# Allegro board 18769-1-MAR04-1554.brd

Outline 198 x 90 mm; copper layers: TOP, TOP_-MB, L2GND, L3_-MB, L3, L4VCC, L5_-MB, L5, L6_-MB, L6, L7VCC, L8_-MB, L8, L9GND, BOTTOM_-MB, BOTTOM. Coordinates in mm from the lower left corner of the outline.

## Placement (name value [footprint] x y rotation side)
AFTP2402  AFTE14P-GP  [AFTE14P-75]  26.02 6.33 0 top
AFTP2507  AFTE14P-GP  [AFTE14P-75]  17.26 9.08 90 top
AFTP2508  AFTE14P-GP  [AFTE14P-75]  16.06 7.47 90 top
AFTP2601  AFTE14P-GP  [AFTE14P-75]  190.34 36.67 270 top
AFTP2602  AFTE14P-GP  [AFTE14P-75]  190.06 34.76 270 top
AFTP2603  AFTE14P-GP  [AFTE14P-75]  189.4 38.35 349 top
AFTP2604  AFTE14P-GP  [AFTE14P-75]  191.05 33.08 270 top
AFTP2901  AFTE14P-GP  [AFTE14P-75]  159.87 11 0 top
AFTP2902  AFTE14P-GP  [AFTE14P-75]  161.34 12.3 0 top
AFTP2903  AFTE14P-GP  [AFTE14P-75]  165.65 10.14 270 top
AFTP2904  AFTE14P-GP  [AFTE14P-75]  162.7 10.92 270 top
AFTP3301  AFTE14P-GP  [AFTE14P-75]  15.4 4.28 0 top
AFTP3302  AFTE14P-GP  [AFTE14P-75]  17.38 4.8 0 top
AFTP4301  AFTE14P-GP  [AFTE14P-75]  36.43 72.73 0 top
AFTP4302  AFTE14P-GP  [AFTE14P-75]  34.91 73.97 0 top
AFTP4303  AFTE14P-GP  [AFTE14P-75]  36.03 81.16 0 top
AFTP4304  AFTE14P-GP  [AFTE14P-75]  32.77 72.66 0 top
AFTP4305  AFTE14P-GP  [AFTE14P-75]  35.07 79.43 0 top
AFTP4306  AFTE14P-GP  [AFTE14P-75]  111.37 9.74 0 top
AFTP4307  AFTE14P-GP  [AFTE14P-75]  117.04 4.11 0 top
AFTP4308  AFTE14P-GP  [AFTE14P-75]  73.1 6.85 270 top
AFTP4309  AFTE14P-GP  [AFTE14P-75]  112.69 14.19 0 top
AFTP4310  AFTE14P-GP  [AFTE14P-75]  109.62 13.57 0 top
AFTP4311  AFTE14P-GP  [AFTE14P-75]  109.61 11.43 0 top
AFTP4312  AFTE14P-GP  [AFTE14P-75]  114.62 6.28 180 top
AFTP4313  AFTE14P-GP  [AFTE14P-75]  112.7 6.14 0 top
AFTP4314  AFTE14P-GP  [AFTE14P-75]  110.79 6.33 180 top
AFTP4316  AFTE14P-GP  [AFTE14P-75]  34.1 81.08 0 top
AFTP4317  AFTE14P-GP  [AFTE14P-75]  195.78 14.36 0 top
AFTP5001  AFTE14P-GP  [AFTE14P-75]  95.4 82.19 270 bottom
AFTP6108  AFTE14P-GP  [AFTE14P-75]  168.46 18.75 270 top
AFTP6109  AFTE14P-GP  [AFTE14P-75]  159.08 17.43 270 top
AFTP6110  AFTE14P-GP  [AFTE14P-75]  170.49 16.29 270 top
AFTP6111  AFTE14P-GP  [AFTE14P-75]  163.66 19.61 270 top
AFTP6112  AFTE14P-GP  [AFTE14P-75]  166.98 20.92 270 top
AFTP6113  AFTE14P-GP  [AFTE14P-75]  167.46 31.67 270 top
AFTP6114  AFTE14P-GP  [AFTE14P-75]  165.66 19.41 270 top
AFTP6115  AFTE14P-GP  [AFTE14P-75]  157.52 16.15 270 top
AFTP6301  AFTE14P-GP  [AFTE14P-75]  119.8 29.31 0 top
AFTP6303  AFTE14P-GP  [AFTE14P-75]  124.98 32.49 180 bottom
AFTP6304  AFTE14P-GP  [AFTE14P-75]  115.48 19.14 0 top
AFTP6501  AFTE14P-GP  [AFTE14P-75]  43.11 4.82 0 top
AFTP6502  AFTE14P-GP  [AFTE14P-75]  38.24 3.31 0 top
AFTP6503  AFTE14P-GP  [AFTE14P-75]  39.25 4.98 0 top
AFTP6504  AFTE14P-GP  [AFTE14P-75]  60.66 5.7 0 top
AFTP6505  AFTE14P-GP  [AFTE14P-75]  41.17 5.03 0 top
AFTP6506  AFTE14P-GP  [AFTE14P-75]  40.99 7.05 0 top
AFTP6507  AFTE14P-GP  [AFTE14P-75]  51.79 8.64 0 top
AFTP6508  AFTE14P-GP  [AFTE14P-75]  41.47 9.02 0 top
AFTP6509  AFTE14P-GP  [AFTE14P-75]  42.93 6.86 0 top
AFTP6510  AFTE14P-GP  [AFTE14P-75]  45.23 9.1 0 top
AFTP6511  AFTE14P-GP  [AFTE14P-75]  50.3 6.63 0 top
AFTP6512  AFTE14P-GP  [AFTE14P-75]  44.88 6.87 0 top
AFTP6513  AFTE14P-GP  [AFTE14P-75]  50.16 4.65 0 top
AFTP6514  AFTE14P-GP  [AFTE14P-75]  46.55 5.78 0 top
AFTP6515  AFTE14P-GP  [AFTE14P-75]  46.95 10.09 0 top
AFTP6516  AFTE14P-GP  [AFTE14P-75]  48.42 6.12 0 top
AFTP6517  AFTE14P-GP  [AFTE14P-75]  47.85 4.29 0 top
AFTP6518  AFTE14P-GP  [AFTE14P-75]  49.14 8.17 0 top
AFTP6519  AFTE14P-GP  [AFTE14P-75]  52.02 5.72 0 top
AFTP6520  AFTE14P-GP  [AFTE14P-75]  54.77 6.39 0 top
AFTP6521  AFTE14P-GP  [AFTE14P-75]  56.35 5.21 0 top
AFTP6522  AFTE14P-GP  [AFTE14P-75]  59.21 4.22 0 top
AFTP6523  AFTE14P-GP  [AFTE14P-75]  58.34 5.99 0 top
AFTP6524  AFTE14P-GP  [AFTE14P-75]  54.48 2.58 0 top
AFTP6525  AFTE14P-GP  [AFTE14P-75]  132.41 7.36 0 top
AFTP6529  AFTE14P-GP  [AFTE14P-75]  21.11 9.74 180 top
AFTP6530  AFTE14P-GP  [AFTE14P-75]  33.93 10.22 0 bottom
AFTP6531  AFTE14P-GP  [AFTE14P-75]  120.79 7.63 0 top
AFTP6534  AFTE14P-GP  [AFTE14P-75]  126.71 10.8 0 bottom
AFTP6535  AFTE14P-GP  [AFTE14P-75]  124.3 9.51 0 bottom
AFTP6536  AFTE14P-GP  [AFTE14P-75]  118.88 4.66 0 top
AFTP6537  AFTE14P-GP  [AFTE14P-75]  125.84 8.44 0 top
AFTP6538  AFTE14P-GP  [AFTE14P-75]  62.05 4.3 180 top
AFTP6539  AFTE14P-GP  [AFTE14P-75]  53.71 4.72 0 top
AFTP6607  AFTE14P-GP  [AFTE14P-75]  162.03 14.41 0 top
AFTP6608  AFTE14P-GP  [AFTE14P-75]  171.53 8.99 0 top
BATT1  ACES-CON12-12-GP-U1  [88231-1201-LP]  107.59 6.16 180 bottom
BIOS1  W25Q128JVSIQ-GP  [SOIC8-1H86]  133.76 27.46 270 bottom
C801  SC1U10V2KX-1DLGP  [C402H22]  97.12 73.19 0 bottom
C802  SC1U10V2KX-1DLGP  [C402H22]  93.88 64.4 90 top
C803  SC1U10V2KX-1DLGP  [C402H22]  97.88 49.85 0 top
C804  SC1U10V2KX-1DLGP  [C402H22]  78.45 36.61 270 top
C805  SCD1U16V2KX-3DLGP  [C402H22]  100.17 59.17 0 top
C806  SC1U10V2KX-1DLGP  [C402H22]  100.96 59.15 0 top
C807  SC22U6D3V3MX-1-DL-GP  [C603H40]  138.57 87.82 180 top
C1102  SC1U10V2KX-1DLGP  [C402H22]  74.21 49.79 90 top
C1103  SC1U10V2KX-1DLGP  [C402H22]  69.49 47.17 90 top
C1104  SC1U10V2KX-1DLGP  [C402H22]  67.53 52.59 90 top
C1105  SC1U10V2KX-1DLGP  [C402H22]  72.35 61.42 180 top
C1106  SC1U10V2KX-1DLGP  [C402H22]  71.72 53.52 90 top
C1107  SC1U10V2KX-1DLGP  [C402H22]  69.48 52.63 270 top
C1108  SC1U10V2KX-1DLGP  [C402H22]  97.88 55.36 0 top
C1109  SC1U10V2KX-1DLGP  [C402H22]  98.03 56.5 270 top
C1110  SC1U10V2KX-1DLGP  [C402H22]  96 51.9 270 top
C1111  SC1U10V2KX-1DLGP  [C402H22]  96.02 52.68 270 top
C1112  SC22U6D3V3MX-1-DL-GP  [C603H40]  100.09 57.21 270 top
C1113  SC22U6D3V3MX-1-DL-GP  [C603H40]  112.23 47.13 270 top
C1114  SC1U10V2KX-1DLGP  [C402H22]  101.56 54.09 0 top
C1115  SC22U6D3V3MX-1-DL-GP  [C603H40]  132.21 86.42 270 top
C1116  SC1U10V2KX-1DLGP  [C402H22]  110.77 87.81 180 top
C1117  SC1U10V2KX-1DLGP  [C402H22]  134.76 87.32 180 top
C1118  SC22U6D3V3MX-1-DL-GP  [C603H40]  137.35 87.82 180 top
C1119  SC1U10V2KX-1DLGP  [C402H22]  105.29 58.29 180 top
C1120  SC10U6D3V3MX-DL-GP  [C603H36]  136.11 87.75 180 top
C1121  SC1U10V2KX-1DLGP  [C402H22]  104.53 58.29 180 top
C1122  SC22U6D3V3MX-1-DL-GP  [C603H40]  105.62 54.68 270 top
C1123  SC10U6D3V3MX-DL-GP  [C603H36]  105.9 50.43 0 top
C1128  SC22U6D3V3MX-1-DL-GP  [C603H40]  99.48 54.91 270 top
C1129  SC22U6D3V3MX-1-DL-GP  [C603H40]  102.6 55.75 180 top
C1130  SC22U6D3V3MX-1-DL-GP  [C603H40]  54.04 35.87 90 top
C1131  SC22U6D3V3MX-1-DL-GP  [C603H40]  84.15 35.8 180 top
C1132  SC22U6D3V3MX-1-DL-GP  [C603H40]  86.75 34.25 180 top
C1133  SC22U6D3V3MX-1-DL-GP  [C603H40]  94.04 49.86 270 top
C1134  SC22U6D3V3MX-1-DL-GP  [C603H40]  84.27 49.76 270 top
C1135  SC22U6D3V3MX-1-DL-GP  [C603H40]  86.65 49.76 90 top
C1136  SC10U6D3V3MX-DL-GP  [C603H36]  82.46 47.17 270 top
C1137  SC10U6D3V3MX-DL-GP  [C603H36]  73.42 33.55 180 top
C1138  SC10U6D3V3MX-DL-GP  [C603H36]  87.47 36.17 270 top
C1139  SCD1U16V2KX-3DLGP  [C402H22]  77.93 46.43 180 top
C1140  SCD1U16V2KX-3DLGP  [C402H22]  91.84 35.53 180 top
C1141  SCD1U16V2KX-3DLGP  [C402H22]  78.59 35.58 270 top
C1142  SCD1U16V2KX-3DLGP  [C402H22]  95.82 24.34 0 top
C1201  SC10U6D3V3MX-DL-GP  [C603H36]  100.74 20.47 270 top
C1209  SC10U6D3V3MX-DL-GP  [C603H36]  58.31 35.76 135 top
C1210  SC10U6D3V3MX-DL-GP  [C603H36]  99.91 26.98 270 top
C1211  SC10U6D3V3MX-DL-GP  [C603H36]  96.86 28.17 90 top
C1214  SCD047U25V2KX-4-GP  [C402H22]  59.52 24.82 0 top
C1215  SCD047U25V2KX-4-GP  [C402H22]  52.03 35.62 270 top
C1218  SC1U10V2KX-1DLGP  [C402H22]  60.54 29.14 180 top
C1219  SC1U10V2KX-1DLGP  [C402H22]  110.54 32.55 270 top
C1220  SC1U10V2KX-1DLGP  [C402H22]  93.81 31.81 270 top
C1221  SC1U10V2KX-1DLGP  [C402H22]  98.91 25.57 180 top
C1226  SC1U10V2KX-1DLGP  [C402H22]  78.83 24.31 0 top
C1227  SC1U10V2KX-1DLGP  [C402H22]  98.14 25.57 180 top
C1229  SCD047U25V2KX-4-GP  [C402H22]  78.46 20.11 270 top
C1230  SCD047U25V2KX-4-GP  [C402H22]  70.32 31.81 270 top
C1231  SC1U10V2KX-1DLGP  [C402H22]  62.95 25.84 0 top
C1242  SC1U10V2KX-1DLGP  [C402H22]  62.08 30.69 270 top
C1244  SC1U10V2KX-1DLGP  [C402H22]  79.97 25.84 180 top
C1245  SC10U6D3V3MX-DL-GP  [C603H36]  70.32 35.36 270 top
C1247  SC10U6D3V3MX-DL-GP  [C603H36]  49.84 38.04 0 bottom
C1248  SC10U6D3V3MX-DL-GP  [C603H36]  96.86 26.98 90 top
C1249  SC10U6D3V3MX-DL-GP  [C603H36]  81.57 26.52 270 top
C1250  SCD022U16V2KX-3DLGP  [C402H22]  63.26 35.76 0 top
C1251  SCD022U16V2KX-3DLGP  [C402H22]  62.12 34.56 90 top
C1252  SC10U6D3V3MX-DL-GP  [C603H36]  77.66 22.61 90 top
C1253  SC10U6D3V3MX-DL-GP  [C603H36]  96.61 19.49 90 top
C1256  SC1U10V2KX-1DLGP  [C402H22]  115.41 25.37 90 top
C1257  SC1U10V2KX-1DLGP  [C402H22]  59.37 29.89 90 top
C1258  SC1U10V2KX-1DLGP  [C402H22]  59.37 30.68 90 top
C1259  SC1U10V2KX-1DLGP  [C402H22]  42.89 35.74 270 top
C1260  SC1U10V2KX-1DLGP  [C402H22]  42.89 34.98 270 top
C1261  SC1U10V2KX-1DLGP  [C402H22]  42.89 34.22 270 top
C1262  SC1U10V2KX-1DLGP  [C402H22]  42.89 33.46 270 top
C1263  SC1U10V2KX-1DLGP  [C402H22]  96.86 29.14 90 top
C1265  SC10U6D3V3MX-DL-GP  [C603H36]  59.52 21.9 270 top
C1266  SC10U6D3V3MX-DL-GP  [C603H36]  80.16 18.26 90 top
C1268  SC1U10V2KX-1DLGP  [C402H22]  58 20.38 180 top
C1269  SC1U10V2KX-1DLGP  [C402H22]  95.47 16.69 180 top
C1270  SC1U10V2KX-1DLGP  [C402H22]  80.19 16.56 180 top
C1271  SC1U10V2KX-1DLGP  [C402H22]  80.99 16.57 180 top
C1275  SC1U10V2KX-1DLGP  [C402H22]  76.03 35.23 180 top
C1276  SC1U10V2KX-1DLGP  [C402H22]  58.38 22.92 90 top
C1277  SC1U10V2KX-1DLGP  [C402H22]  77.57 20.87 90 top
C1278  SC1U10V2KX-1DLGP  [C402H22]  61.56 20.63 270 top
C1279  SC1U10V2KX-1DLGP  [C402H22]  58.38 23.68 90 top
C1304  SC1U10V2KX-1DLGP  [C402H22]  81.55 22.03 270 top
C1310  SC1U10V2KX-1DLGP  [C402H22]  81.57 28.71 270 top
C1311  SC1U10V2KX-1DLGP  [C402H22]  51.9 38.41 180 top
C1312  SC1U10V2KX-1DLGP  [C402H22]  73.37 31.81 90 top
C1313  SC1U10V2KX-1DLGP  [C402H22]  96.61 24.31 0 top
C1314  SCD047U25V2KX-4-GP  [C402H22]  80.35 21.14 180 top
C1315  SCD047U25V2KX-4-GP  [C402H22]  108.29 31.81 270 top
C1317  SC1U10V2KX-1DLGP  [C402H22]  77.57 19.35 90 top
C1322  SC10U6D3V3MX-DL-GP  [C603H36]  62.19 29.65 270 top
C1323  SC1U10V2KX-1DLGP  [C402H22]  71.84 31.81 90 top
C1324  SC1U10V2KX-1DLGP  [C402H22]  105.24 31.81 270 top
C1325  SC1U10V2KX-1DLGP  [C402H22]  51.14 38.41 180 top
C1326  SC1U10V2KX-1DLGP  [C402H22]  110.54 31.79 270 top
C1329  SCD047U25V2KX-4-GP  [C402H22]  58.76 24.82 0 top
C1330  SCD047U25V2KX-4-GP  [C402H22]  88.23 31.81 270 top
C1331  SC1U10V2KX-1DLGP  [C402H22]  79.21 25.84 180 top
C1332  SC1U10V2KX-1DLGP  [C402H22]  97.38 25.57 180 top
C1333  SC10U6D3V3MX-DL-GP  [C603H36]  59.22 34.96 135 top
C1334  SC10U6D3V3MX-DL-GP  [C603H36]  115.69 24.3 90 top
C1338  SC10U6D3V3MX-DL-GP  [C603H36]  96.61 20.76 90 top
C1339  SCD022U16V2KX-3DLGP  [C402H22]  66.82 35.91 90 top
C1341  SC1U10V2KX-1DLGP  [C402H22]  82.26 24.31 0 top
C1342  SC1U10V2KX-1DLGP  [C402H22]  99.91 29.14 270 top
C1343  SC1U10V2KX-1DLGP  [C402H22]  90.39 34.98 270 top
C1344  SC1U10V2KX-1DLGP  [C402H22]  98.77 29.52 0 top
C1348  SC1U10V2KX-1DLGP  [C402H22]  100.59 19.47 270 top
C1349  SC1U10V2KX-1DLGP  [C402H22]  44.13 27.79 270 top
C1350  SC10U6D3V3MX-DL-GP  [C603H36]  78.45 28.5 90 top
C1351  SC10U6D3V3MX-DL-GP  [C603H36]  99.91 28.17 270 top
C1352  SC1U10V2KX-1DLGP  [C402H22]  98.01 29.52 0 top
C1353  SC1U10V2KX-1DLGP  [C402H22]  99.67 25.57 180 top
C1354  SC1U10V2KX-1DLGP  [C402H22]  101.82 24.31 0 top
C1355  SC1U10V2KX-1DLGP  [C402H22]  80.86 35.49 180 top
C1356  SC10U6D3V3MX-DL-GP  [C603H36]  61.56 19.61 270 top
C1367  SC1U10V2KX-1DLGP  [C402H22]  98.68 16.57 180 top
C1368  SC1U10V2KX-1DLGP  [C402H22]  98.77 18.6 90 top
C1369  SC1U10V2KX-1DLGP  [C402H22]  57.16 20.33 180 top
C1370  SC1U10V2KX-1DLGP  [C402H22]  45.05 19.11 270 top
C1371  SC10U6D3V3MX-DL-GP  [C603H36]  97.62 23.08 180 top
C1372  SC10U6D3V3MX-DL-GP  [C603H36]  59.18 18.79 90 top
C1605  SCD22U16V2KX-DL-GP  [C402H22]  108.75 72.65 90 bottom
C1606  SCD22U16V2KX-DL-GP  [C402H22]  108.75 73.41 90 bottom
C1607  SCD22U16V2KX-DL-GP  [C402H22]  108.75 74.3 90 bottom
C1608  SCD22U16V2KX-DL-GP  [C402H22]  108.75 75.06 90 bottom
C1609  SCD22U16V2KX-DL-GP  [C402H22]  108.75 75.82 90 bottom
C1610  SCD22U16V2KX-DL-GP  [C402H22]  108.75 76.59 90 bottom
C1611  SCD22U16V2KX-DL-GP  [C402H22]  108.75 77.35 90 bottom
C1612  SCD22U16V2KX-DL-GP  [C402H22]  108.75 78.11 90 bottom
C1701  SC220P50V2KX-3DLGP  [C402H22]  131.24 49.07 90 bottom
C1711  SCD1U16V2KX-3DLGP  [C402H22]  91.5 72.74 90 bottom
C1803  SC15P50V2JN-DL-GP  [C402H22]  107.17 36.6 90 top
C1804  SC15P50V2JN-DL-GP  [C402H22]  104.05 36.6 270 top
C1805  SC1U10V2KX-1DLGP  [C402H22]  118.04 26.1 0 top
C1806  SC1U10V2KX-1DLGP  [C402H22]  102.02 38.29 180 bottom
C1807  SC15P50V2JN-DL-GP  [C402H22]  116.26 73.22 270 bottom
C1808  SC15P50V2JN-DL-GP  [C402H22]  114.53 73.22 90 bottom
C2201  SCD1U16V2KX-3DLGP  [C402H22]  99.58 51.63 0 top
C2202  SC1U10V2KX-1DLGP  [C402H22]  106.16 53.26 180 top
C2203  SC1U10V2KX-1DLGP  [C402H22]  104.16 51.64 0 top
C2204  SC1U10V2KX-1DLGP  [C402H22]  107.53 51.76 180 top
C2205  SC1U10V2KX-1DLGP  [C402H22]  112.22 48.46 180 top
C2206  SCD1U16V2KX-3DLGP  [C402H22]  111.45 48.45 180 top
C2207  SCD1U16V2KX-3DLGP  [C402H22]  110.68 48.45 180 top
C2208  SC22U6D3V3MX-1-DL-GP  [C603H40]  105.49 74.51 270 top
C2209  SC1U10V2KX-1DLGP  [C402H22]  105.65 75.49 270 top
C2210  SC1U10V2KX-1DLGP  [C402H22]  105.57 56.26 270 top
C2211  SC1U10V2KX-1DLGP  [C402H22]  106.74 56.87 180 top
C2212  SC1U10V2KX-1DLGP  [C402H22]  106.41 58.03 90 top
C2213  SC1U10V2KX-1DLGP  [C402H22]  102.54 51.16 90 top
C2214  SC1U10V2KX-1DLGP  [C402H22]  110 87.82 180 top
C2215  SC1U10V2KX-1DLGP  [C402H22]  134.89 81.44 0 top
C2216  SC1U10V2KX-1DLGP  [C402H22]  135.01 81.54 180 bottom
C2217  SC1U10V2KX-1DLGP  [C402H22]  104.56 53.17 90 top
C2218  SC4D7U6D3V3KX-DLGP  [C603H36]  113.8 49.59 270 top
C2219  SC1U10V2KX-1DLGP  [C402H22]  112.22 63.49 0 top
C2220  SC22U6D3V3MX-1-DL-GP  [C603H40]  104.9 60.82 90 top
C2221  SCD1U16V2KX-3DLGP  [C402H22]  102.52 51.94 90 top
C2222  SC1U10V2KX-1DLGP  [C402H22]  109.06 55.33 270 top
C2223  SC1U10V2KX-1DLGP  [C402H22]  98.86 53.53 180 top
C2224  SC1U10V2KX-1DLGP  [C402H22]  102 49.76 90 top
C2405  SC100P50V2JN-3DLGP  [C402H22]  18.97 12.36 0 top
C2406  SCD1U16V2KX-3DLGP  [C402H22]  14.72 12.17 90 bottom
C2407  SCD1U16V2KX-3DLGP  [C402H22]  17.19 19.23 270 top
C2408  SCD1U16V2KX-3DLGP  [C402H22]  15.33 20.31 0 bottom
C2410  SCD1U16V2KX-3DLGP  [C402H22]  16.67 14.09 0 top
C2411  SCD1U16V2KX-3DLGP  [C402H22]  17.48 14.08 0 top
C2412  SCD1U16V2KX-3DLGP  [C402H22]  25.14 28.76 0 top
C2413  SCD1U16V2KX-3DLGP  [C402H22]  31.7 21.17 0 top
C2414  SCD1U16V2KX-3DLGP  [C402H22]  19.07 28.06 270 top
C2415  SCD1U16V2KX-3DLGP  [C402H22]  25.93 28.78 0 top
C2416  SCD1U16V2KX-3DLGP  [C402H22]  11.64 18.91 90 bottom
C2418  SC1U10V2KX-1DLGP  [C402H22]  24.57 27.05 0 top
C2421  SCD1U16V2KX-3DLGP  [C402H22]  11.64 18.15 90 bottom
C2422  SCD1U16V2KX-3DLGP  [C402H22]  15.14 21 0 top
C2423  SCD1U16V2KX-3DLGP  [C402H22]  35.1 18.62 270 bottom
C2424  SC18P50V2JN-1DLGP  [C402H22]  14.41 25.56 0 bottom
C2425  SC18P50V2JN-1DLGP  [C402H22]  14.41 24.03 180 bottom
C2427  SC2D2U10V3KX-1DLGP-U  [C603H36]  15.66 27.71 0 bottom
C2428  SCD1U16V2KX-3DLGP  [C402H22]  23.05 26.01 180 top
C2429  SCD1U16V2KX-3DLGP  [C402H22]  22.19 12.8 180 top
C2435  SC2200P50V2KX-2DLGP  [C402H22]  17.11 20.04 270 top
C2436  SC2200P50V2KX-2DLGP  [C402H22]  36.95 16.01 270 bottom
C2441  SC2200P50V2KX-2DLGP  [C402H22]  17.11 20.82 270 top
C2501  SC10U6D3V3MX-DL-GP  [C603H36]  127.74 30.14 90 bottom
C2502  SCD1U16V2KX-3DLGP  [C402H22]  128.04 31.2 90 bottom
C2503  SCD1U16V2KX-3DLGP  [C402H22]  18.86 9.16 0 bottom
C2517  SCD022U16V2KX-3DLGP  [C402H22]  23.83 5.43 90 top
C2525  SC1U10V2KX-1DLGP  [C402H22]  169.94 34.31 180 top
C2601  SC10U6D3V3MX-DL-GP  [C603H36]  125.49 41.89 0 bottom
C2602  SCD1U16V2KX-3DLGP  [C402H22]  128.5 33.89 0 bottom
C2604  SC4D7U6D3V3KX-DLGP  [C603H36]  193.04 38.43 90 top
C2605  SCD1U16V2KX-3DLGP  [C402H22]  192.23 35.82 0 top
C2606  SC470P50V2KX-3DLGP  [C402H22]  94.65 80.54 270 bottom
C2607  SC2200P50V2KX-2DLGP  [C402H22]  126.83 41.42 270 bottom
C2608  SCD1U16V2KX-3DLGP  [C402H22]  123.24 39.08 0 bottom
C2609  SCD1U16V2KX-3DLGP  [C402H22]  123.24 37.6 180 bottom
C2610  SCD1U16V2KX-3DLGP  [C402H22]  128.08 45.99 180 top
C2702  SC2D2U10V3KX-1DLGP-U  [C603H36]  188.33 12.69 270 top
C2703  SC2D2U10V3KX-1DLGP-U  [C603H36]  188.32 11.5 90 top
C2704  SCD1U16V2KX-3DLGP  [C402H22]  187.68 18.14 90 top
C2705  SC2D2U10V3KX-1DLGP-U  [C603H36]  188.12 17.15 90 top
C2706  SCD1U16V2KX-3DLGP  [C402H22]  185.94 11.4 270 top
C2707  SC10U6D3V3MX-DL-GP  [C603H36]  187.38 9.5 90 top
C2708  SC2D2U10V3KX-1DLGP-U  [C603H36]  189.88 17.6 0 top
C2709  SC2D2U10V3KX-1DLGP-U  [C603H36]  187.8 15.77 270 top
C2710  SC10U6D3V3MX-DL-GP  [C603H36]  187.02 20.34 180 top
C2711  SC10U6D3V3MX-DL-GP  [C603H36]  188.19 20.31 0 top
C2713  SC10U6D3V3MX-DL-GP  [C603H36]  184.33 22.31 180 top
C2714  SCD1U16V2KX-3DLGP  [C402H22]  184.52 20.67 90 top
C2715  SC10U6D3V3MX-DL-GP  [C603H36]  182.32 9.93 0 top
C2717  SC10U6D3V3MX-DL-GP  [C603H36]  180.38 21 270 top
C2718  SCD1U16V2KX-3DLGP  [C402H22]  179.97 20.03 270 top
C2720  SC10U6D3V3MX-DL-GP  [C603H36]  177.01 19.5 270 top
C2721  SCD1U16V2KX-3DLGP  [C402H22]  177.45 18.5 270 top
C2722  SC10U6D3V3MX-DL-GP  [C603H36]  176.67 14.72 270 top
C2723  SC4D7U6D3V3KX-DLGP  [C603H36]  175.82 10.56 0 top
C2735  SCD1U16V2KX-3DLGP  [C402H22]  180.5 10.56 180 top
C2739  SC100P50V2JN-3DLGP  [C402H22]  176.21 8.96 270 top
C2740  SC2D2U10V3KX-1DLGP-U  [C603H36]  172.76 12.78 270 top
C2741  SCD1U16V2KX-3DLGP  [C402H22]  177.87 10.98 0 top
C2907  SC10U6D3V3MX-DL-GP  [C603H36]  185.5 9.31 0 top
C2908  SC10U6D3V3MX-DL-GP  [C603H36]  184.31 9.31 0 top
C2909  SC10U6D3V3MX-DL-GP  [C603H36]  180.48 9.05 90 top
C3301  SC6P50V2CN-1-NL-GP  [C402H22]  6.77 18.06 270 bottom
C3302  SC4D7U6D3V3KX-DLGP  [C603H36]  4.01 13.72 90 bottom
C3303  SCD1U16V2KX-3DLGP  [C402H22]  3.74 10.31 90 bottom
C3304  SC2D2U10V3KX-1DLGP-U  [C603H36]  6.55 7.86 180 bottom
C3305  SCD1U16V2KX-3DLGP  [C402H22]  7.55 7.63 180 bottom
C3307  SC2D2U10V3KX-1DLGP-U  [C603H36]  2 8.86 90 bottom
C3308  SCD1U16V2KX-3DLGP  [C402H22]  1.72 9.85 90 bottom
C3309  SCD1U16V2KX-3DLGP  [C402H22]  11.87 16.07 0 bottom
C3310  SC1U10V2KX-1DLGP  [C402H22]  3.52 15.85 90 bottom
C3311  SC1U10V2KX-1DLGP  [C402H22]  7.98 17.77 0 bottom
C3312  SC4D7U6D3V3KX-DLGP  [C603H36]  3.95 11.28 90 bottom
C3313  SC6P50V2CN-1-NL-GP  [C402H22]  5.59 8.01 180 bottom
C4001  SC470P50V2KX-3DLGP  [C402H22]  62 11.4 90 bottom
C4002  SC470P50V2KX-3DLGP  [C402H22]  62 10.59 90 bottom
C4003  SCD22U10V2KX-2-GP  [C402H22]  68.5 10.8 270 bottom
C4004  SC10U25V5KX-DL-GP  [C805H58]  60.27 10.36 0 bottom
C4005  SC10U25V5KX-DL-GP  [C805H58]  58.51 11.67 180 bottom
C4006  SC10U6D3V3MX-DL-GP  [C603H36]  103.28 32.06 90 top
C4007  SCD1U16V2KX-3DLGP  [C402H22]  93.97 34.45 270 top
C4008  SC10U6D3V3MX-DL-GP  [C603H36]  112.41 87.08 90 top
C4009  SC2D2U10V3KX-1DLGP-U  [C603H36]  12.74 28.44 180 top
C4010  SCD1U16V2KX-3DLGP  [C402H22]  107.83 81.23 270 top
C4012  SC10U6D3V3MX-DL-GP  [C603H36]  138.64 84.09 0 top
C4013  SC10U6D3V3MX-DL-GP  [C603H36]  132.21 85.21 270 top
C4031  SC1U10V2KX-1DLGP  [C402H22]  132.89 84.19 270 top
C4032  SC1U10V2KX-1DLGP  [C402H22]  100.32 33.85 0 top
C4034  SCD1U16V2KX-3DLGP  [C402H22]  132.45 82.9 0 top
C4035  SC1U10V2KX-1DLGP  [C402H22]  89.92 33.73 180 top
C4037  SCD1U16V2KX-3DLGP  [C402H22]  195.63 16.39 90 top
C4038  SC1U10V2KX-1DLGP  [C402H22]  194.42 15.6 270 top
C4039  SCD1U16V2KX-3DLGP  [C402H22]  195.02 17.33 90 top
C4040  SCD1U25V2KX-1-DL-GP  [C402H22]  107.12 86.93 180 top
C4043  SC1U10V2KX-1DLGP  [C402H22]  108.32 86.19 270 top
C4301  SC1U50V3KX-1-GP  [C603H36]  30.44 79.8 270 top
C4302  SCD1U25V2KX-1-DL-GP  [C402H22]  32.32 79.66 180 top
C4303  SCD01U25V2KX-3DLGP  [C402H22]  27.33 79.09 180 top
C4304  SCD01U25V2KX-3DLGP  [C402H22]  28.86 79.6 180 top
C4305  SCD01U25V2KX-3DLGP  [C402H22]  28.1 79.6 180 top
C4306  SC10U25V5KX-DL-GP  [C805H58]  26.3 70.1 270 bottom
C4344  SC1KP50V2KX-1DLGP  [C402H22]  35.93 60.32 90 bottom
C5501  SCD1U16V2KX-3DLGP  [C402H22]  46.53 76.12 0 top
C5502  SC4D7U6D3V3KX-DLGP  [C603H36]  63.26 76.51 0 bottom
C5503  SC4D7U6D3V3KX-DLGP  [C603H36]  57.61 80.84 0 top
C5504  SCD1U16V2KX-3DLGP  [C402H22]  47.31 76.13 0 top
C5505  SC22U6D3V3MX-1-DL-GP  [C603H40]  58.24 76 0 bottom
C5506  SCD1U16V2KX-3DLGP  [C402H22]  44.95 76.13 0 top
C5507  SCD1U16V2KX-3DLGP  [C402H22]  39.95 81.87 270 top
C5508  SC1U10V2KX-1DLGP  [C402H22]  39.96 81.11 270 top
C5509  SCD1U16V2KX-3DLGP  [C402H22]  45.71 76.13 0 top
C5510  SCD1U16V2KX-3DLGP  [C402H22]  43.42 76.13 0 top
C5511  SCD1U16V2KX-3DLGP  [C402H22]  44.18 76.13 0 top
C5512  SCD1U25V2KX-1-DL-GP  [C402H22]  40.47 76.38 270 bottom
C5513  SC1KP50V2KX-1DLGP  [C402H22]  40.6 77.38 270 bottom
C5514  SC10U25V5KX-DL-GP  [C805H58]  40.25 74.83 270 bottom
C5515  SC4D7U6D3V3KX-DLGP  [C603H36]  58.44 76.22 270 top
C5516  SCD1U16V2KX-3DLGP  [C402H22]  60.36 82.58 180 top
C5517  SC10U6D3V3MX-DL-GP  [C603H36]  62.19 82.83 90 top
C5518  SC10U6D3V3MX-DL-GP  [C603H36]  59.01 82.74 180 top
C5554  SCD1U16V2KX-3DLGP  [C402H22]  39.33 72.83 180 top
C5555  SC2200P50V2KX-2DLGP  [C402H22]  38.55 72.95 180 top
C5556  SCD1U25V2KX-1-DL-GP  [C402H22]  38.01 81.13 180 top
C5557  SC2200P50V2KX-2DLGP  [C402H22]  49.92 73.03 270 bottom
C5558  SCD1U16V2KX-3DLGP  [C402H22]  39.76 74.33 270 top
C5701  SCD1U16V2KX-3DLGP  [C402H22]  21.95 42.75 270 bottom
C5702  SCD1U16V2KX-3DLGP  [C402H22]  23.74 53.27 270 top
C5703  SCD1U16V2KX-3DLGP  [C402H22]  23.74 52.51 270 top
C5704  SCD1U16V2KX-3DLGP  [C402H22]  23.74 54.92 270 top
C5705  SCD1U16V2KX-3DLGP  [C402H22]  23.74 54.16 270 top
C5706  SCD1U16V2KX-3DLGP  [C402H22]  23.86 51.49 270 top
C5707  SCD1U16V2KX-3DLGP  [C402H22]  23.86 50.73 270 top
C5708  SCD1U16V2KX-3DLGP  [C402H22]  23.86 49.97 270 top
C5709  SCD1U16V2KX-3DLGP  [C402H22]  23.86 49.2 270 top
C5710  SCD1U16V2KX-3DLGP  [C402H22]  14.64 63.66 270 bottom
C6104  SC10U6D3V3MX-DL-GP  [C603H36]  168.79 30.02 90 top
C6105  SCD1U16V2KX-3DLGP  [C402H22]  170.01 14.32 90 top
C6106  SCD01U25V2KX-3DLGP  [C402H22]  169.99 31.64 90 top
C6107  SCD1U16V2KX-3DLGP  [C402H22]  157.44 24.44 0 bottom
C6108  SCD1U16V2KX-3DLGP  [C402H22]  158.2 24.44 0 bottom
C6109  SC10U6D3V3MX-DL-GP  [C603H36]  167.9 14.91 180 top
C6110  SCD1U16V2KX-3DLGP  [C402H22]  169.81 13.5 90 top
C6111  SCD01U25V2KX-3DLGP  [C402H22]  168.82 32.08 180 top
C6302  SCD22U10V2KX-2-GP  [C402H22]  126.37 27.85 270 bottom
C6303  SCD22U10V2KX-2-GP  [C402H22]  126.37 27.09 270 bottom
C6304  SC33P50V2JN-3DLGP  [C402H22]  115.87 32.42 270 top
C6305  SC33P50V2JN-3DLGP  [C402H22]  115.87 31.64 270 top
C6306  SCD047U25V2KX-4-GP  [C402H22]  115.18 16.39 270 top
C6307  SCD1U16V2KX-3DLGP  [C402H22]  115.9 30.81 270 top
C6308  SCD047U25V2KX-4-GP  [C402H22]  115.16 17.18 270 top
C6311  SCD22U10V2KX-2-GP  [C402H22]  125.95 24.96 270 bottom
C6312  SCD22U10V2KX-2-GP  [C402H22]  125.95 24.2 270 bottom
C6313  SCD22U10V2KX-2-GP  [C402H22]  127.05 23.38 270 bottom
C6314  SCD22U10V2KX-2-GP  [C402H22]  127.05 22.62 270 bottom
C6315  SCD22U10V2KX-2-GP  [C402H22]  127.13 21.81 270 bottom
C6316  SCD22U10V2KX-2-GP  [C402H22]  127.13 21.05 270 bottom
C6317  SC22U6D3V3MX-1-DL-GP  [C603H40]  115.72 21.93 180 top
C6318  SC22U6D3V3MX-1-DL-GP  [C603H40]  116.92 21.93 180 top
C6401  SCD1U16V2KX-3DLGP  [C402H22]  9.14 72.93 90 top
C6402  SC1U10V2KX-1DLGP  [C402H22]  16.88 66.76 270 top
C6501  SCD1U16V2KX-3DLGP  [C402H22]  20.6 10 90 bottom
C6504  SCD1U16V2KX-3DLGP  [C402H22]  24.28 6.34 270 top
C6505  SCD1U16V2KX-3DLGP  [C402H22]  118.75 6.72 270 top
C6701  SC1U10V2KX-1DLGP  [C402H22]  15.27 47.3 0 bottom
C6702  SC1U10V2KX-1DLGP  [C402H22]  15.5 43.65 180 bottom
C6703  SC1U10V2KX-1DLGP  [C402H22]  15.69 45.7 180 bottom
C6715  SCD1U16V2KX-3DLGP  [C402H22]  13.22 46.62 0 top
C7005  SCD1U16V2KX-3DLGP  [C402H22]  193.54 32.09 270 top
C7006  SC10U6D3V3MX-DL-GP  [C603H36]  193.23 33.08 270 top
C7101  SCD1U25V2KX-1-DL-GP  [C402H22]  19.27 42.6 180 top
C7102  SCD1U25V2KX-1-DL-GP  [C402H22]  18.5 42.6 180 top
C7103  SCD1U16V2KX-3DLGP  [C402H22]  21.88 30.9 180 top
C7104  SCD1U16V2KX-3DLGP  [C402H22]  21.12 30.9 180 top
C7105  SCD1U16V2KX-3DLGP  [C402H22]  20.35 30.9 180 top
C7106  SCD1U16V2KX-3DLGP  [C402H22]  19.59 30.9 180 top
C7107  SCD1U16V2KX-3DLGP  [C402H22]  24.47 35.82 270 top
C7108  SCD1U16V2KX-3DLGP  [C402H22]  24.47 37.35 270 top
C7109  SCD1U16V2KX-3DLGP  [C402H22]  24.47 36.59 270 top
C7110  SCD1U16V2KX-3DLGP  [C402H22]  24.47 38.87 270 top
C7111  SCD1U16V2KX-3DLGP  [C402H22]  24.47 38.11 270 top
C7112  SCD1U16V2KX-3DLGP  [C402H22]  23.99 31.66 270 top
C7113  SCD1U16V2KX-3DLGP  [C402H22]  23.99 32.42 270 top
C7114  SCD1U16V2KX-3DLGP  [C402H22]  24.47 35.06 270 top
C7115  SCD1U25V2KX-1-DL-GP  [C402H22]  17.92 28.33 0 top
C7116  SCD1U25V2KX-1-DL-GP  [C402H22]  17.23 38.23 180 bottom
C7117  SCD1U25V2KX-1-DL-GP  [C402H22]  23.36 41.2 180 top
C7118  SCD1U25V2KX-1-DL-GP  [C402H22]  18.11 34.23 0 bottom
C7119  SC10U6D3V3MX-DL-GP  [C603H36]  18.22 37.82 180 bottom
C7120  SCD33U6D3V1MX-GP  [C0201H13]  12.94 38.33 270 top
C7121  SCD33U6D3V1MX-GP  [C0201H13]  12.94 37.57 270 top
C7122  SCD33U6D3V1MX-GP  [C0201H13]  12.9 29.93 270 top
C7123  SCD33U6D3V1MX-GP  [C0201H13]  12.89 30.7 270 top
C7161  SCD1U25V2KX-1-DL-GP  [C402H22]  16.77 33.07 0 top
C7162  SCD1U25V2KX-1-DL-GP  [C402H22]  16.01 33.07 0 top
C7163  SCD1U25V2KX-1-DL-GP  [C402H22]  16.22 35.95 270 top
C7164  SCD1U25V2KX-1-DL-GP  [C402H22]  16.22 36.71 270 top
C7201  SC2D2U10V3KX-1DLGP-U  [C603H36]  31.76 63.83 180 top
C7202  SC2D2U10V3KX-1DLGP-U  [C603H36]  28.89 65.89 180 top
C7203  SC2D2U10V3KX-1DLGP-U  [C603H36]  31.84 57.46 90 bottom
C7205  SC22U6D3V3MX-1-DL-GP  [C603H40]  22.12 64.97 90 bottom
C7206  SCD1U16V2KX-3DLGP  [C402H22]  22.25 63.99 90 bottom
C7208  SC10U6D3V3MX-DL-GP  [C603H36]  34.51 61.78 90 bottom
C7210  SC1U10V2KX-1DLGP  [C402H22]  28.43 60.02 270 top
C7211  SC10U6D3V3MX-DL-GP  [C603H36]  32.11 62.03 90 top
C7212  SCD22U10V2KX-2-GP  [C402H22]  26.17 59.7 90 top
C7217  SC220P50V2KX-3DLGP  [C402H22]  21.73 56.57 0 bottom
C7218  SC220P50V2KX-3DLGP  [C402H22]  22.39 56.75 90 top
C7244  SCD1U16V2KX-3DLGP  [C402H22]  36.31 64.11 270 bottom
C7301  SC1U25V3KX-1-DLGP  [C603H36]  22.51 58.55 180 bottom
C7302  SCD1U25V2KX-1-DL-GP  [C402H22]  13.14 30.12 180 bottom
C7303  SCD1U25V2KX-1-DL-GP  [C402H22]  12.36 30.03 180 bottom
C7304  SCD1U25V2KX-1-DL-GP  [C402H22]  13.24 35.76 0 bottom
C7305  SC10U25V5KX-DL-GP  [C805H58]  16.03 32.7 270 bottom
C7306  SC1U25V3KX-1-DLGP  [C603H36]  14.28 36.85 0 bottom
C7307  SCD1U25V2KX-1-DL-GP  [C402H22]  11.6 30.03 180 bottom
C7401  SC1500P50V2KX-2-DL-GP  [C402H22]  19.96 65.53 270 top
C7601  SCD22U16V2KX-DL-GP  [C402H22]  128.87 67.75 90 top
C7602  SCD22U16V2KX-DL-GP  [C402H22]  128.87 66.98 90 top
C7603  SCD22U16V2KX-DL-GP  [C402H22]  128.87 69.27 90 top
C7604  SCD22U16V2KX-DL-GP  [C402H22]  128.87 68.51 90 top
C7605  SCD22U16V2KX-DL-GP  [C402H22]  128.87 70.79 90 top
C7606  SCD22U16V2KX-DL-GP  [C402H22]  128.87 70.03 90 top
C7607  SCD22U16V2KX-DL-GP  [C402H22]  128.84 71.64 90 top
C7608  SCD22U16V2KX-DL-GP  [C402H22]  128.84 72.4 90 top
C7610  SC4D7U6D3V3KX-DLGP  [C603H36]  162.17 85.81 270 bottom
C7611  SC4D7U6D3V3KX-DLGP  [C603H36]  162.17 84.6 270 bottom
C7612  SC1U10V2KX-1DLGP  [C402H22]  161.91 87.61 270 bottom
C7613  SC1U10V2KX-1DLGP  [C402H22]  161.89 86.82 270 bottom
C7614  SC1U10V2KX-1DLGP  [C402H22]  149.4 63.18 225 top
C7616  SCD1U25V2KX-1-DL-GP  [C402H22]  156.79 69.67 315 top
C7620  SC4D7U6D3V3KX-DLGP  [C603H36]  157.26 84.36 203 top
C7621  SC4D7U6D3V3KX-DLGP  [C603H36]  158.36 84.81 203 top
C7622  SC1U10V2KX-1DLGP  [C402H22]  155.37 71.28 315 top
C7627  SC10U6D3V3MX-DL-GP  [C603H36]  156.76 84.12 0 bottom
C7628  SC22U6D3V3MX-1-DL-GP  [C603H40]  157.94 84.12 0 bottom
C7629  SC10U6D3V3MX-DL-GP  [C603H36]  159.13 84.14 0 bottom
C7630  SC1U10V2KX-1DLGP  [C402H22]  158.25 68.61 315 top
C7631  SC1U10V2KX-1DLGP  [C402H22]  154.23 70.62 225 top
C7744  SC10U6D3V3MX-DL-GP  [C603H36]  154.12 66.95 315 top
C7745  SC10U6D3V3MX-DL-GP  [C603H36]  157.4 44.12 315 bottom
C7746  SC10U6D3V3MX-DL-GP  [C603H36]  162.29 37.89 90 bottom
C7805  SCD1U16V2KX-3DLGP  [C402H22]  162.9 64.65 180 top
C7807  SC1U10V2KX-1DLGP  [C402H22]  174.41 86.39 0 bottom
C7808  SCD1U16V2KX-3DLGP  [C402H22]  161.96 63.89 0 top
C7810  SC1U10V2KX-1DLGP  [C402H22]  170.55 86.39 0 bottom
C7811  SC1U10V2KX-1DLGP  [C402H22]  171.34 86.39 0 bottom
C7812  SC1U10V2KX-1DLGP  [C402H22]  184.06 69.13 180 bottom
C7815  SC1U10V2KX-1DLGP  [C402H22]  188.94 64.13 90 bottom
C7816  SC1U10V2KX-1DLGP  [C402H22]  174.91 51.26 90 bottom
C7817  SC10U6D3V3MX-DL-GP  [C603H36]  185.07 62.52 0 bottom
C7818  SC22U6D3V3MX-1-DL-GP  [C603H40]  160.29 61.22 225 top
C7819  SC10U6D3V3MX-DL-GP  [C603H36]  183 86.59 0 bottom
C7820  SC22U6D3V3MX-1-DL-GP  [C603H40]  184.27 86.59 0 bottom
C7821  SC22U6D3V3MX-1-DL-GP  [C603H40]  185.54 86.59 0 bottom
C7822  SC22U6D3V3MX-1-DL-GP  [C603H40]  181.8 86.57 0 bottom
C7823  SC10U6D3V3MX-DL-GP  [C603H36]  180.61 86.57 0 bottom
C7825  SC1U10V2KX-1DLGP  [C402H22]  175.22 86.39 0 bottom
C7826  SC1U10V2KX-1DLGP  [C402H22]  186.04 62.57 0 bottom
C7827  SCD1U16V2KX-3DLGP  [C402H22]  162.59 66.4 0 top
C7902  SCD1U16V2KX-3DLGP  [C402H22]  159.08 56.68 315 top
C7905  SCD1U16V2KX-3DLGP  [C402H22]  160.16 55.49 45 top
C7906  SCD1U16V2KX-3DLGP  [C402H22]  160.44 58.33 135 top
C7907  SC20P50V2JN-1-DL-GP  [C402H22]  175.81 41.09 270 bottom
C7908  SC20P50V2JN-1-DL-GP  [C402H22]  172.61 41.09 90 bottom
C7934  SC4D7U6D3V3KX-DLGP  [C603H36]  154.06 60.17 135 top
C7935  SC22U6D3V3MX-1-DL-GP  [C603H40]  155.8 57.84 45 top
C8001  SC4D7U6D3V3KX-DLGP  [C603H36]  163.3 37.29 0 top
C8002  SC4D7U6D3V3KX-DLGP  [C603H36]  156.88 38.8 180 bottom
C8003  SC4D7U6D3V3KX-DLGP  [C603H36]  159.44 85.27 203 top
C8004  SC4D7U6D3V3KX-DLGP  [C603H36]  158.73 59.35 135 top
C8008  SC4D7U6D3V3KX-DLGP  [C603H36]  144.25 42.75 0 top
C8009  SC4D7U6D3V3KX-DLGP  [C603H36]  135.67 42.74 0 top
C8010  SC22U6D3V3MX-1-DL-GP  [C603H40]  154.99 69.44 315 top
C8011  SC1U10V2KX-1DLGP  [C402H22]  162.58 34.93 90 bottom
C8012  SC1U10V2KX-1DLGP  [C402H22]  162.28 36.71 90 bottom
C8013  SC1U10V2KX-1DLGP  [C402H22]  145.25 42.76 0 top
C8014  SC1U10V2KX-1DLGP  [C402H22]  155.56 68.5 315 top
C8015  SC4D7U6D3V3KX-DLGP  [C603H36]  157.29 37.31 0 top
C8016  SC4D7U6D3V3KX-DLGP  [C603H36]  158.56 37.31 0 top
C8017  SC22U6D3V3MX-1-DL-GP  [C603H40]  158.05 38.81 180 bottom
C8018  SC1U10V2KX-1DLGP  [C402H22]  142.21 42.66 0 top
C8019  SC4D7U6D3V3KX-DLGP  [C603H36]  147.56 42.62 0 top
C8020  SC4D7U6D3V3KX-DLGP  [C603H36]  138.04 48.28 180 top
C8021  SC4D7U6D3V3KX-DLGP  [C603H36]  136.77 48.28 180 top
C8022  SC4D7U6D3V3KX-DLGP  [C603H36]  152.35 65.31 315 top
C8023  SC4D7U6D3V3KX-DLGP  [C603H36]  159.24 38.81 180 bottom
C8024  SC4D7U6D3V3KX-DLGP  [C603H36]  153.29 67.79 315 top
C8025  SC4D7U6D3V3KX-DLGP  [C603H36]  156.05 60.5 315 top
C8027  SC22U6D3V3MX-1-DL-GP  [C603H40]  160.43 38.83 180 bottom
C8028  SC1U10V2KX-1DLGP  [C402H22]  155.1 82.73 201 top
C8029  SCD1U16V2KX-3DLGP  [C402H22]  155.82 83.01 201 top
C8030  SC4D7U6D3V3KX-DLGP  [C603H36]  162.44 33.89 90 bottom
C8031  SC4D7U6D3V3KX-DLGP  [C603H36]  160.58 41.72 315 bottom
C8032  SC4D7U6D3V3KX-DLGP  [C603H36]  157.82 62.39 315 top
C8033  SC22U6D3V3MX-1-DL-GP  [C603H40]  162.12 37.29 0 top
C8034  SCD1U16V2KX-3DLGP  [C402H22]  156.56 83.3 201 top
C8035  SCD1U16V2KX-3DLGP  [C402H22]  159.46 58.68 135 top
C8036  SC1U10V2KX-1DLGP  [C402H22]  158.54 57.23 315 top
C8037  SCD1U16V2KX-3DLGP  [C402H22]  159.62 54.95 45 top
C8038  SC10U6D3V3MX-DL-GP  [C603H36]  156.88 67.17 315 top
C8039  SC10U6D3V3MX-DL-GP  [C603H36]  155.2 65.48 315 top
C8040  SC10U6D3V3MX-DL-GP  [C603H36]  158.13 65.51 315 top
C8041  SC10U6D3V3MX-DL-GP  [C603H36]  156.42 63.86 315 top
C8042  SC10U6D3V3MX-DL-GP  [C603H36]  154.58 62.35 315 top
C8043  SC10U6D3V3MX-DL-GP  [C603H36]  159.52 64.13 315 top
C8044  SCD1U16V2KX-3DLGP  [C402H22]  158.38 60.45 135 top
C8045  SC10U6D3V3MX-DL-GP  [C603H36]  160.94 37.3 0 top
C8046  SC10U6D3V3MX-DL-GP  [C603H36]  159.75 37.31 0 top
C8101  SCD01U25V2KX-3DLGP  [C402H22]  183.48 42.94 90 top
C8104  SC10U6D3V3MX-DL-GP  [C603H36]  185.05 69.13 180 bottom
C8105  SC1U10V2KX-1DLGP  [C402H22]  187.98 69.15 180 bottom
C8106  SC1U10V2KX-1DLGP  [C402H22]  188.54 65.88 90 bottom
C8107  SC1U10V2KX-1DLGP  [C402H22]  186.82 62.58 0 bottom
C8108  SCD1U16V2KX-3DLGP  [C402H22]  188.38 68 90 bottom
C8109  SC1U10V2KX-1DLGP  [C402H22]  188.38 67.24 90 bottom
C8110  SC1U10V2KX-1DLGP  [C402H22]  184.28 86.15 180 top
C8111  SC1U10V2KX-1DLGP  [C402H22]  183.13 86.1 180 top
C8112  SC1U10V2KX-1DLGP  [C402H22]  181.35 86.1 180 top
C8113  SC10U6D3V3MX-DL-GP  [C603H36]  186.22 69.13 180 bottom
C8114  SC1U10V2KX-1DLGP  [C402H22]  182.11 86.1 180 top
C8115  SCD1U16V2KX-3DLGP  [C402H22]  169.73 86.38 0 bottom
C8116  SCD1U16V2KX-3DLGP  [C402H22]  168.97 86.38 0 bottom
C8117  SCD1U16V2KX-3DLGP  [C402H22]  174.8 86.73 180 top
C8118  SCD1U16V2KX-3DLGP  [C402H22]  173.65 86.39 0 bottom
C8119  SCD1U16V2KX-3DLGP  [C402H22]  172.11 86.38 0 bottom
C8120  SCD1U16V2KX-3DLGP  [C402H22]  172.87 86.38 0 bottom
C8121  SCD1U16V2KX-3DLGP  [C402H22]  177.23 86.78 180 top
C8122  SCD1U16V2KX-3DLGP  [C402H22]  176.39 86.82 180 top
C8123  SCD1U16V2KX-3DLGP  [C402H22]  175.6 86.76 180 top
C8124  SCD1U16V2KX-3DLGP  [C402H22]  184.03 62.52 0 bottom
C8125  SCD1U16V2KX-3DLGP  [C402H22]  170.97 86.73 180 top
C8126  SC820P50V2KX-1-DL-GP  [C402H22]  176.01 86.39 0 bottom
C8201  SCD01U25V2KX-3DLGP  [C402H22]  180.28 87.23 90 top
C8202  SC820P50V2KX-1-DL-GP  [C402H22]  176.81 86.4 0 bottom
C8204  SC1U10V2KX-1DLGP  [C402H22]  187.27 45.43 180 bottom
C8205  SC1U10V2KX-1DLGP  [C402H22]  184.49 45.42 180 bottom
C8206  SC1U10V2KX-1DLGP  [C402H22]  185.27 45.42 180 bottom
C8207  SC10U6D3V3MX-DL-GP  [C603H36]  188.81 62.54 0 bottom
C8209  SCD1U16V2KX-3DLGP  [C402H22]  188.99 58.74 270 top
C8210  SCD1U16V2KX-3DLGP  [C402H22]  176.78 68.37 0 top
C8211  SCD1U16V2KX-3DLGP  [C402H22]  188.05 45.43 180 bottom
C8212  SCD1U16V2KX-3DLGP  [C402H22]  187.61 62.58 0 bottom
C8213  SCD1U16V2KX-3DLGP  [C402H22]  186.14 44.33 0 top
C8214  SCD1U16V2KX-3DLGP  [C402H22]  185.38 44.33 0 top
C8215  SC1U10V2KX-1DLGP  [C402H22]  180.67 44.36 0 top
C8216  SC1U10V2KX-1DLGP  [C402H22]  179.9 44.36 0 top
C8217  SC1U10V2KX-1DLGP  [C402H22]  179.14 44.36 0 top
C8218  SC10U6D3V3MX-DL-GP  [C603H36]  186.27 45.41 180 bottom
C8219  SC1U10V2KX-1DLGP  [C402H22]  178.38 44.36 0 top
C8220  SCD1U16V2KX-3DLGP  [C402H22]  177.62 44.36 0 top
C8221  SCD1U16V2KX-3DLGP  [C402H22]  176.86 44.36 0 top
C8222  SCD1U16V2KX-3DLGP  [C402H22]  176.09 44.36 0 top
C8223  SCD1U16V2KX-3DLGP  [C402H22]  181.43 44.36 0 top
C8224  SC1U10V2KX-1DLGP  [C402H22]  175.33 44.36 0 top
C8225  SCD1U16V2KX-3DLGP  [C402H22]  174.57 44.36 0 top
C8226  SCD1U16V2KX-3DLGP  [C402H22]  186.32 75.8 90 top
C8525  SCD1U25V2KX-1-DL-GP  [C402H22]  146.56 29.59 270 top
C8601  SCD1U16V2KX-3DLGP  [C402H22]  132.12 74.46 0 bottom
C8602  SCD1U16V2KX-3DLGP  [C402H22]  129.38 72.77 270 bottom
C8603  SCD1U16V2KX-3DLGP  [C402H22]  148.57 81.27 180 top
C8604  SCD1U16V2KX-3DLGP  [C402H22]  133.32 73 270 bottom
C8901  SC10U25V3MX-5-GP  [C603H40]  63.64 5.4 180 top
C8902  SC10U25V3MX-5-GP  [C603H40]  75.47 10.41 90 top
C8903  SC10U25V3MX-5-GP  [C603H40]  41.07 10.75 270 top
C9104  SCD1U16V2KX-3DLGP  [C402H22]  188.14 31.74 180 top
C9106  SC10U6D3V3MX-DL-GP  [C603H36]  189.27 25.93 90 top
C9108  SCD1U16V2KX-3DLGP  [C402H22]  188.84 26.94 90 top
C9109  SC10U6D3V3MX-DL-GP  [C603H36]  179.32 27.09 0 top
C9112  SCD1U16V2KX-3DLGP  [C402H22]  180.35 27.58 0 top
C9113  SCD1U16V2KX-3DLGP  [C402H22]  181.17 27.58 0 top
C9201  SC1U10V2KX-1DLGP  [C402H22]  144.4 7.7 90 top
CARD1  SDCARD-8P-10-GP  [503398-0891]  1.32 13.6 90 top
CN1  HRS-CONN20A-2-GP  [DF30FC-20DP-D4V-81]  123.65 75.27 0 bottom
CPU1  WHISKEY-LAKE-GP  [BGA1528M2446-1H52]  90.15 54.21 270 bottom
D1701  RB520S30-GP  [SOD523AKH26]  129.91 56.87 270 bottom
D2401  BAT54C-12-GP  [SOT-23-9H44]  22.48 21.69 90 top
D2402  RB751VM-40TE-17-GP  [SOD323-2513AKH36]  36.04 13.82 90 bottom
D2403  L1SS355T1G-GP  [SOD323AKH44]  23.47 18.28 90 top
D2501  BAT54C-12-GP  [SOT-23-9H44]  16.49 9.27 90 bottom
D2503  BAT54A-11-GP  [SOT-23-9H44]  174.9 33.35 0 top
D2703  BAT54C-12-GP  [SOT-23-9H44]  171.81 5.7 0 top
D2901  BAW56-9-GP-U  [SOT23-2D4-312H44]  191.03 14.6 180 top
D4001  L1SS355T1G-GP  [SOD323AKH44]  12.07 21.1 90 top
D4301  P6AF24A-R1-00001-GP  [D4724AKH44]  39.61 78.66 270 top
D4302  LBAV99LT1G-1-GP  [SOT23-2D4-312H44]  18.37 50.74 0 bottom
D4303  L30ESD24VC3-2-GP  [SOT23-2D4-312H60]  24.27 53.23 180 bottom
D4304  SMF18A-GP  [SOD123AK-2H43]  119.35 4.99 0 bottom
D5501  BAT54C-12-GP  [SOT-23-9H44]  64.6 84.36 270 bottom
D5502  BAT54C-12-GP  [SOT-23-9H44]  63.67 86.97 90 top
D5504  RB551V30-GP  [SOD323AKH38]  37.66 68.11 180 bottom
D5505  RB551V30-GP  [SOD323AKH38]  39.39 70.74 270 top
D5701  BAW56-9-GP-U  [SOT23-2D4-312H44]  14.92 68.17 270 bottom
D6401  BAT54A-11-GP  [SOT-23-9H44]  21.11 73.2 180 top
D6402  RB751V-40-2-GP  [SOD323AKH38]  19.94 65.02 0 bottom
D6701  L1SS355T1G-GP  [SOD323AKH44]  17.55 44.21 180 bottom
D6702  RB751VM-40TE-17-GP  [SOD323-2513AKH36]  20.39 47.35 270 top
D7301  BX310F-R1-00000-GP  [D4724AKH44]  16.39 30.37 90 bottom
D7902  L1SS355T1G-GP  [SOD323AKH44]  160.09 44.39 225 bottom
D8601  BAT54C-12-GP  [SOT-23-9H44]  185.03 40.09 270 bottom
DB1  ACES-CON14-5-GP  [87212-1400N]  26.58 19.17 90 top
DB3  ACES-CON6-58-GP  [50696-00601-001]  33.89 8.79 90 top
DCIN1  ACES-CON8-13-GP-U2  [50224-0080N-W02-U]  31.1 76.6 90 bottom
EC1901  SC10P50V2JN-4DLGP  [C402H22]  119.64 37.26 270 bottom
EC2201  SCD1U16V2KX-3DLGP  [C402H22]  109.23 87.86 180 top
EC2501  SC10P50V2JN-4DLGP  [C402H22]  125.83 25.81 90 bottom
EC2601  SC10P50V2JN-4DLGP  [C402H22]  188.66 36.14 180 top
EC2602  SC10P50V2JN-4DLGP  [C402H22]  188.66 34.39 0 top
EC2701  SC1KP50V2KX-1DLGP  [C402H22]  190.72 9.44 0 top
EC2702  SC1KP50V2KX-1DLGP  [C402H22]  189.96 9.44 0 top
EC2703  SC1KP50V2KX-1DLGP  [C402H22]  181.25 7.66 0 top
EC2704  SC1KP50V2KX-1DLGP  [C402H22]  192.57 16.58 90 top
EC2705  SC1KP50V2KX-1DLGP  [C402H22]  192.57 17.37 90 top
EC2706  SC33P50V2JN-3DLGP  [C402H22]  175.68 17.31 270 top
EC2709  SC22P50V2JN-9-GP  [C402H22]  174.51 16.96 180 top
EC2710  SC22P50V2JN-9-GP  [C402H22]  174.02 15.26 90 top
EC2711  SC22P50V2JN-9-GP  [C402H22]  174.22 18.15 270 top
EC2901  SC1KP50V2KX-1DLGP  [C402H22]  160.52 9.27 90 top
EC2902  SC1KP50V2KX-1DLGP  [C402H22]  158.96 9.65 270 top
EC2903  SC1KP50V2KX-1DLGP  [C402H22]  163.65 9.29 270 top
EC2904  SC1KP50V2KX-1DLGP  [C402H22]  162.14 9.29 90 top
EC4301  SC10U25V5KX-DL-GP  [C805H58]  37 76.06 180 bottom
EC4302  SCD1U25V2KX-1-DL-GP  [C402H22]  36.52 76.27 0 top
EC4303  SCD1U25V2KX-1-DL-GP  [C402H22]  22.34 59.49 270 top
EC4306  SC10P50V2JN-4DLGP  [C402H22]  86.45 14.27 90 top
EC4307  SC1KP50V2KX-1DLGP  [C402H22]  99 12.45 90 bottom
EC4308  SCD1U50V3KX-DL-GP  [C603H35]  98.78 11.44 90 bottom
EC4309  SC10P50V2JN-4DLGP  [C402H22]  112.79 10.74 0 top
EC4310  SC10P50V2JN-4DLGP  [C402H22]  112.79 12.39 180 top
EC4312  SC1KP50V2KX-1DLGP  [C402H22]  37.28 76.27 0 top
EC4401  SC1KP50V2KX-1DLGP  [C402H22]  35.35 71.85 0 bottom
EC4402  SC1KP50V2KX-1DLGP  [C402H22]  25.8 39.04 0 bottom
EC4403  SC1KP50V2KX-1DLGP  [C402H22]  135.22 7.56 0 top
EC4404  SC1KP50V2KX-1DLGP  [C402H22]  134.43 7.56 0 top
EC4405  SC1KP50V2KX-1DLGP  [C402H22]  39.95 10.83 90 bottom
EC4406  SC1KP50V2KX-1DLGP  [C402H22]  135.37 3.19 180 bottom
EC4407  SC1KP50V2KX-1DLGP  [C402H22]  64.65 3.31 180 bottom
EC4408  SC1KP50V2KX-1DLGP  [C402H22]  74.23 11.66 0 bottom
EC5503  SC33P50V2JN-3DLGP  [C402H22]  54.45 78.96 270 top
EC5504  SC33P50V2JN-3DLGP  [C402H22]  57.19 78.45 0 top
EC6401  SC10P50V2JN-4DLGP  [C402H22]  7.82 69.71 180 bottom
EC6402  SC10P50V2JN-4DLGP  [C402H22]  8.43 72.98 270 bottom
EC6501  SC33P50V2JN-3DLGP  [C402H22]  127.88 5.96 0 top
EC6502  SC33P50V2JN-3DLGP  [C402H22]  127.88 7.48 180 top
EC8901  SCD1U16V2KX-3DLGP  [C402H22]  100.68 73.33 180 bottom
EC8902  SCD1U16V2KX-3DLGP  [C402H22]  76.44 72.17 180 bottom
EC8903  SCD1U16V2KX-3DLGP  [C402H22]  77.25 72.15 180 bottom
EC8904  SCD1U16V2KX-3DLGP  [C402H22]  86.63 72.9 180 bottom
EC8905  SCD1U16V2KX-3DLGP  [C402H22]  49.11 56.34 270 top
EC8906  SCD1U16V2KX-3DLGP  [C402H22]  49.11 55.48 270 top
EC8907  SCD1U16V2KX-3DLGP  [C402H22]  104.33 76.38 90 top
EC8908  SCD1U25V2KX-1-DL-GP  [C402H22]  41.52 39.5 90 top
EC8909  SCD1U25V2KX-1-DL-GP  [C402H22]  41.81 70.04 225 top
EC8910  SCD1U25V2KX-1-DL-GP  [C402H22]  134.38 38.54 90 top
EC8911  SCD1U25V2KX-1-DL-GP  [C402H22]  134.89 61.77 45 bottom
EC8912  SCD1U25V2KX-1-DL-GP  [C402H22]  64.3 77.55 180 bottom
EC8913  SCD1U25V2KX-1-DL-GP  [C402H22]  156.73 35.62 90 top
EC8914  SCD1U25V2KX-1-DL-GP  [C402H22]  186.73 33.3 0 top
EC8915  SCD1U25V2KX-1-DL-GP  [C402H22]  130.44 38.05 0 bottom
EC8916  SCD1U25V2KX-1-DL-GP  [C402H22]  101.79 87.18 270 bottom
EC8917  SCD1U25V2KX-1-DL-GP  [C402H22]  40.94 44.63 90 top
EC8918  SC1KP50V2KX-1DLGP  [C402H22]  24.52 64.95 0 top
EC8919  SC1KP50V2KX-1DLGP  [C402H22]  51.88 12.37 270 bottom
EC8920  SC1KP50V2KX-1DLGP  [C402H22]  64.2 2.88 270 top
EC8921  SC1KP50V2KX-1DLGP  [C402H22]  33.11 28.83 270 bottom
EC8922  SC1KP50V2KX-1DLGP  [C402H22]  26.81 34.45 270 top
EC8923  SC1KP50V2KX-1DLGP  [C402H22]  189.24 24.92 90 top
EC8924  SC1KP50V2KX-1DLGP  [C402H22]  163.38 15.04 180 top
EC8925  SC1KP50V2KX-1DLGP  [C402H22]  90.87 8.82 270 top
EC8926  SC1KP50V2KX-1DLGP  [C402H22]  66.26 11.99 0 top
EC8927  SC1KP50V2KX-1DLGP  [C402H22]  169.86 10.34 270 top
EC8928  SC1KP50V2KX-1DLGP  [C402H22]  64.22 2.11 270 top
EC8929  SC1KP50V2KX-1DLGP  [C402H22]  69.25 9.66 0 bottom
EC8930  SC1KP50V2KX-1DLGP  [C402H22]  80.81 24.31 0 top
EC8931  SC1KP50V2KX-1DLGP  [C402H22]  63.74 25.58 0 top
EC8932  SC1KP50V2KX-1DLGP  [C402H22]  79.64 24.31 0 top
EC8933  SC1KP50V2KX-1DLGP  [C402H22]  42.94 32.64 270 top
EC8934  SC1KP50V2KX-1DLGP  [C402H22]  52.67 38.41 180 top
EC8937  SCD1U16V2KX-3DLGP  [C402H22]  85.82 72.92 180 bottom
EC8938  SCD1U16V2KX-3DLGP  [C402H22]  83.35 72.32 180 bottom
EC8939  SC1KP50V2KX-1DLGP  [C402H22]  50.28 38.41 180 top
EC8940  SC1KP50V2KX-1DLGP  [C402H22]  92.63 35.52 180 top
EC8941  SC1KP50V2KX-1DLGP  [C402H22]  101.11 32.68 180 top
EC8942  SC1KP50V2KX-1DLGP  [C402H22]  70.68 36.4 270 top
EC8943  SC1KP50V2KX-1DLGP  [C402H22]  32.58 82.05 270 top
EC8944  SC1KP50V2KX-1DLGP  [C402H22]  64.55 11.87 0 top
EC8945  SC1KP50V2KX-1DLGP  [C402H22]  60.03 76.64 0 top
EC8946  SC1KP50V2KX-1DLGP  [C402H22]  119.95 17.23 90 top
EC8947  SC1KP50V2KX-1DLGP  [C402H22]  127.11 81.79 270 top
EC8948  SC1KP50V2KX-1DLGP  [C402H22]  16.45 57.08 90 top
EC8949  SC1KP50V2KX-1DLGP  [C402H22]  194.43 35.83 0 top
EC8950  SC1KP50V2KX-1DLGP  [C402H22]  179.72 23.44 0 top
EC8951  SC1KP50V2KX-1DLGP  [C402H22]  16.57 59.35 90 top
EC8952  SC1KP50V2KX-1DLGP  [C402H22]  61.94 10.11 270 top
EC8953  SC1KP50V2KX-1DLGP  [C402H22]  188.71 7.19 90 top
EC8954  SC1KP50V2KX-1DLGP  [C402H22]  22.35 5.46 0 top
ED301  AZ5125-02S-R7G-GP  [SOT23-2D4-312H46]  95.02 75.02 270 bottom
ED1701  TVL5VB1-DFN1006-2L-GP  [SOD882-10D6-1H20]  131.17 58.75 0 bottom
ED1702  TVL5VB1-DFN1006-2L-GP  [SOD882-10D6-1H20]  175.94 31.04 0 top
ED1703  TVL5VB1-DFN1006-2L-GP  [SOD882-10D6-1H20]  127.7 53.69 180 top
ED1704  TVL5VB1-DFN1006-2L-GP  [SOD882-10D6-1H20]  72.45 12.3 90 bottom
ED1706  AZ5725-01FDR7G-GP  [SOD882-10D6-1H20]  131.5 52.63 180 bottom
ED1707  AZ5725-01FDR7G-GP  [SOD882-10D6-1H20]  93.1 71.38 270 bottom
ED4304  LBAV99LT1G-1-GP  [SOT23-2D4-312H44]  80.12 11.55 0 top
ED4305  LBAV99LT1G-1-GP  [SOT23-2D4-312H44]  115.7 11.3 180 top
ED4306  LBAV99LT1G-1-GP  [SOT23-2D4-312H44]  115.69 8.79 180 top
ED5501  AZC099-04S-2-GP  [SOT-6H58]  53.75 74.64 90 bottom
ED5502  PUSB3F96-GP  [DFN10G2510-1H20]  48.73 75.75 180 bottom
ED5503  AZ5725-01FDR7G-GP  [SOD882-10D6-1H20]  51.81 77.36 0 top
ED5504  AZ5725-01FDR7G-GP  [SOD882-10D6-1H20]  109.06 59.78 270 top
ED5701  L05ESDL5V0NA-4-GP  [SLP2510P8-1H22]  18.76 53.65 90 top
ED5702  L05ESDL5V0NA-4-GP  [SLP2510P8-1H22]  18.5 50.47 90 top
ED5703  L05ESDL5V0NA-4-GP  [SLP2510P8-1H22]  15.28 63.33 180 top
ED6701  AZ5725-01FDR7G-GP  [SOD882-10D6-1H20]  116.28 5.5 90 top
ED7301  L05ESDL5V0NA-4-GP  [SLP2510P8-1H22]  14.58 37.13 90 top
ED7302  L05ESDL5V0NA-4-GP  [SLP2510P8-1H22]  14.57 31.12 90 top
ED7303  L05ESDL5V0NA-4-GP  [SLP2510P8-1H22]  12.72 40.88 0 top
ED7304  L05ESDL5V0NA-4-GP  [SLP2510P8-1H22]  16.47 43.47 0 top
ED9201  L05ESDL5V0NA-4-GP  [SLP2510P8-1H22]  137 9.97 0 bottom
EL4301  0R5J-5-GP  [R805H24]  34.07 75.81 270 top
EL4302  0R5J-5-GP  [R805H24]  34.09 77.56 270 top
EL4303  0R5J-5-GP  [R805H24]  37.33 74.56 90 top
EL4304  0R5J-5-GP  [R805H24]  34.59 71.62 0 top
EL5501  DLM0NSN900HY2D-GP  [LD85D65-4P-1H20]  57.26 73.95 90 bottom
EL7201  DLM0NSN900HY2D-GP  [LD85D65-4P-1H20]  27.96 56.45 180 bottom
EL7202  DLM0NSN900HY2D-GP  [LD85D65-4P-1H20]  26.38 56.44 180 bottom
ER2901  0R3J-0-U-GP  [R603H22]  161.61 7.65 180 top
ER2902  0R3J-0-U-GP  [R603H22]  162.88 7.68 180 top
ER2903  0R3J-0-U-GP  [R603H22]  160.1 7.65 180 top
ER2904  0R3J-0-U-GP  [R603H22]  158.82 7.7 180 top
ER5714  150R2J-L1-GP-U  [R402H16]  20.15 52.89 0 top
ER5715  150R2J-L1-GP-U  [R402H16]  20.15 54.54 0 top
ER5716  150R2J-L1-GP-U  [R402H16]  20.02 49.53 0 top
ER5717  150R2J-L1-GP-U  [R402H16]  20.03 51.11 0 top
ER7301  0R5J-5-GP  [R805H24]  20.91 58.73 180 bottom
ER7302  0R5J-5-GP  [R805H24]  19.13 58.76 180 bottom
F5502  POLYSW-1D1A6V-9-GP-U  [POLYSW-2114H30]  60.09 78.85 180 top
F5503  POLYSW-1D1A24V-GP-U  [POLYSW-4633-UH43]  39.07 72.04 90 bottom
F5701  POLYSW-1D1A6V-9-GP-U  [POLYSW-2114H30]  15.43 60.69 270 top
F6501  POLYSW-1D1A6V-10-GP  [POLYSW-2114H30]  20.5 8.09 0 bottom
FAN1  ACES-CON4-29-GP  [50224-0040N-001]  191.6 36.5 270 bottom
FC8901  SCD1U25V2KX-1-DL-GP  [C402H22]  161.33 40.9 315 bottom
FC8902  SCD1U25V2KX-1-DL-GP  [C402H22]  139.53 48.36 0 bottom
FC8903  SCD1U25V2KX-1-DL-GP  [C402H22]  129.25 41.81 90 bottom
FC8904  SCD1U25V2KX-1-DL-GP  [C402H22]  129.22 41.01 90 bottom
FC8905  SCD1U25V2KX-1-DL-GP  [C402H22]  143.12 42.86 0 top
FC8906  SCD1U25V2KX-1-DL-GP  [C402H22]  82.77 2.21 180 bottom
FC8907  SCD1U25V2KX-1-DL-GP  [C402H22]  83.73 6.19 270 bottom
FC8908  SCD1U25V2KX-1-DL-GP  [C402H22]  186.81 33.72 270 bottom
FC8909  SCD1U25V2KX-1-DL-GP  [C402H22]  44.57 72.54 0 bottom
FC8910  SCD1U25V2KX-1-DL-GP  [C402H22]  43.37 66.39 90 top
FC8911  SCD1U25V2KX-1-DL-GP  [C402H22]  42.89 64.58 90 top
FC8912  SCD1U25V2KX-1-DL-GP  [C402H22]  163.11 35.34 180 top
FC8913  SCD1U25V2KX-1-DL-GP  [C402H22]  158.09 35.25 180 top
FC8914  SCD1U25V2KX-1-DL-GP  [C402H22]  134.33 42.98 90 top
FC8915  SCD1U25V2KX-1-DL-GP  [C402H22]  134.96 61.18 180 top
FC8916  SCD1U25V2KX-1-DL-GP  [C402H22]  132.5 60.88 180 top
FC8917  SCD1U25V2KX-1-DL-GP  [C402H22]  168.19 86.39 0 bottom
FC8918  SCD1U25V2KX-1-DL-GP  [C402H22]  186.92 85.69 315 bottom
FC8919  SCD1U25V2KX-1-DL-GP  [C402H22]  173.18 86.79 180 top
FC8920  SCD1U25V2KX-1-DL-GP  [C402H22]  173.99 86.75 180 top
FC8921  SCD1U25V2KX-1-DL-GP  [C402H22]  111.98 87.09 0 bottom
FC8922  SCD1U25V2KX-1-DL-GP  [C402H22]  97.17 83.45 270 top
FC8923  SCD1U25V2KX-1-DL-GP  [C402H22]  87.43 72.93 180 bottom
FC8924  SCD1U25V2KX-1-DL-GP  [C402H22]  81.52 72.37 180 bottom
FC8925  SCD1U25V2KX-1-DL-GP  [C402H22]  74.86 72.19 180 bottom
FC8926  SCD1U25V2KX-1-DL-GP  [C402H22]  88.23 72.95 180 bottom
FC8927  SCD1U25V2KX-1-DL-GP  [C402H22]  56.18 48.69 180 bottom
FC8928  SCD1U25V2KX-1-DL-GP  [C402H22]  57.13 61.45 0 bottom
FC8929  SCD1U25V2KX-1-DL-GP  [C402H22]  24.05 42.89 315 top
FC8930  SCD1U25V2KX-1-DL-GP  [C402H22]  24.61 42.33 315 top
FC8931  SCD1U25V2KX-1-DL-GP  [C402H22]  91.29 6.73 0 top
FC8932  SCD1U25V2KX-1-DL-GP  [C402H22]  57.25 12 180 bottom
FC8933  SCD1U25V2KX-1-DL-GP  [C402H22]  67.22 1.68 0 top
FC8934  SCD1U25V2KX-1-DL-GP  [C402H22]  115.55 29.03 90 top
FC8935  SCD1U25V2KX-1-DL-GP  [C402H22]  64.05 33.37 180 top
FC8936  SCD1U25V2KX-1-DL-GP  [C402H22]  62.48 33.37 180 top
FC8937  SCD1U25V2KX-1-DL-GP  [C402H22]  53.49 38.25 180 top
FC8938  SCD1U25V2KX-1-DL-GP  [C402H22]  49.49 38.43 180 top
FC8939  SC12P50V2JN-DL-GP  [C402H22]  161.89 40.36 315 bottom
FC8940  SC12P50V2JN-DL-GP  [C402H22]  130.1 48.23 0 bottom
FC8941  SC12P50V2JN-DL-GP  [C402H22]  162.46 39.77 315 bottom
FC8942  SC12P50V2JN-DL-GP  [C402H22]  146.04 42.78 0 top
FC8943  SC12P50V2JN-DL-GP  [C402H22]  79.83 87.12 270 bottom
FC8944  SC12P50V2JN-DL-GP  [C402H22]  79.82 87.89 270 bottom
FC8945  SC12P50V2JN-DL-GP  [C402H22]  66.31 78.68 90 top
FC8946  SC12P50V2JN-DL-GP  [C402H22]  66.18 76.15 45 top
FC8947  SC12P50V2JN-DL-GP  [C402H22]  48.61 75.06 225 top
FC8948  SC12P50V2JN-DL-GP  [C402H22]  49.15 75.62 225 top
FC8949  SC12P50V2JN-DL-GP  [C402H22]  37.29 41.69 270 top
FC8950  SC12P50V2JN-DL-GP  [C402H22]  36.09 44.38 315 top
FC8951  SC12P50V2JN-DL-GP  [C402H22]  144.64 32.57 180 top
FC8952  SC12P50V2JN-DL-GP  [C402H22]  143.5 32.57 180 top
FC8953  SC12P50V2JN-DL-GP  [C402H22]  134.34 43.76 90 top
FC8954  SC12P50V2JN-DL-GP  [C402H22]  188.55 65.08 90 bottom
FC8955  SC12P50V2JN-DL-GP  [C402H22]  187.2 69.16 180 bottom
FC8956  SC12P50V2JN-DL-GP  [C402H22]  170.18 86.72 180 top
FC8957  SC12P50V2JN-DL-GP  [C402H22]  171.81 86.73 180 top
FC8958  SC12P50V2JN-DL-GP  [C402H22]  117.1 87.14 0 bottom
FC8959  SC12P50V2JN-DL-GP  [C402H22]  101.31 84.73 270 bottom
FC8960  SC12P50V2JN-DL-GP  [C402H22]  75.64 72.16 180 bottom
FC8961  SC12P50V2JN-DL-GP  [C402H22]  92.7 63.2 90 top
FC8962  SC12P50V2JN-DL-GP  [C402H22]  87.36 77.26 180 top
FC8963  SC12P50V2JN-DL-GP  [C402H22]  86.56 77.27 180 top
FC8964  SC12P50V2JN-DL-GP  [C402H22]  57.01 48.67 180 bottom
FC8965  SC12P50V2JN-DL-GP  [C402H22]  57.92 61.47 0 bottom
FC8966  SC12P50V2JN-DL-GP  [C402H22]  70.84 13.02 270 bottom
FC8967  SC12P50V2JN-DL-GP  [C402H22]  92.08 6.74 0 top
FC8968  SC12P50V2JN-DL-GP  [C402H22]  66.3 1.7 0 top
FC8969  SC12P50V2JN-DL-GP  [C402H22]  115.55 28.26 90 top
